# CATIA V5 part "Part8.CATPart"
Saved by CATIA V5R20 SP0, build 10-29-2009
Part number: FV161320-6_Circlip DIN 472 - 13 x 1
Revision: ANY
Definition: UNKNOWN
Nomenclature: FV161320-6_Circlip DIN 472 - 13 x 1
Source: Unknown
Bounding box of the stored display mesh (mm): x -6.8 to 6.8, y -6.599 to 6.63, z -1 to 0
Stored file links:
  C:\Users\Utente\Desktop\IO LAVORO\3D X SITO CF\CUMSA\3D files FV\FV 201720\Part8.CATPart
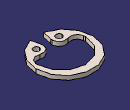
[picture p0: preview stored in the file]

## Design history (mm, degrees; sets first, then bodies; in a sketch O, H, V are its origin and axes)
Body1 "Body" (main body)
  Solid1: solid without history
